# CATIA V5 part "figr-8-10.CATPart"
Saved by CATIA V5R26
Part number: Part2
Bounding box of the stored display mesh (mm): x -37.886 to 37.886, y -61.415 to 61.415, z 29 to 58
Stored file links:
  D:\_Deepak\CATIA\CATIA V5-6R2016_Deepak\Resources\Part files\Partfiles\c08_catia_v5_6r2016_prt\figr-8-10.CATPart
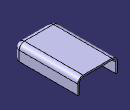
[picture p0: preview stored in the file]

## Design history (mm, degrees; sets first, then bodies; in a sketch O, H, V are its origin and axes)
Body1 (main body)
  Sketch1 on xy-plane, origin (0, 0, 0), H (1, 0, 0), V (0, 1, 0)
    line L1 (37.8862, 61.4155) -> (37.8862, -61.4155)
    line L2 (37.8862, -61.4155) -> (-37.8862, -61.4155)
    line L3 (-37.8862, -61.4155) -> (-37.8862, 61.4155)
    line L4 (-37.8862, 61.4155) -> (37.8862, 61.4155)
    vertical: L1 V, L3 V
    horizontal: L2 H, L4 H
    equidistance: L1 L3 O, L2 L4 O
  Pad1: profile Sketch1, direction (0, 0, 1), length 29
  Fillet1: radius 10, on edge [face of Pad1 | face of Pad1] (x5)
  Shell1: ExtOffset 0, Face (face of Pad1; face of Pad1), IntOffset 3
  Symmetry1: ToTransfor Shell1, Reference face of Pad1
